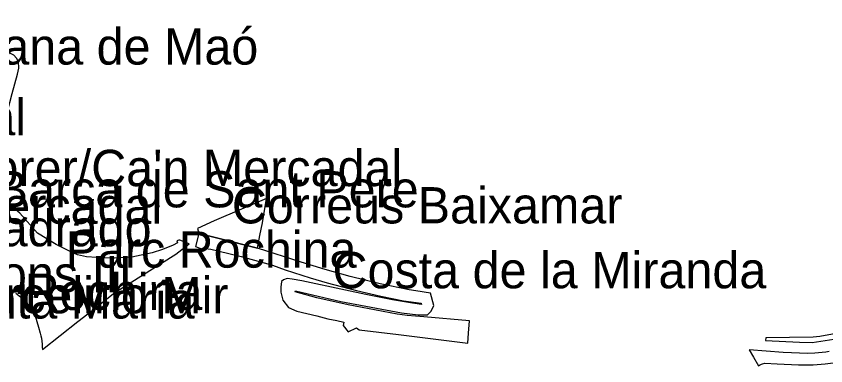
# Model space of a CAD drawing. Extents: x 599451 to 612034, y 4411179 to 4428219.
# Drawn here: x 608246.7 to 608514.7, y 4416232.3 to 4416348 of the extents above; entities that cross this region are included whole.
import ezdxf

# ---------------------------------------------------------------- set-up
doc = ezdxf.new("R2010")
doc.units = 0
doc.layers.add('Elements patrimoni', color=7, linetype='Continuous')
doc.layers.add('Elements patrimonials', color=7, linetype='Continuous')

msp = doc.modelspace()

# ---------------------------------------------------------------- linework, layer by layer
at = {"layer": 'Elements patrimonials'}
for points in [[(608243.71, 4416315.96), (608245.36, 4416322.37), (608247.07, 4416328.77), (608247.51, 4416330.82), (608247.4, 4416332.84), (608246.76, 4416334.12), (608245.84, 4416335.04), (608244.8, 4416335.6), (608243.01, 4416336.08), (608240.46, 4416336.82), (608209.6, 4416345.68), (608201, 4416347.97), (608195.6, 4416328.69), (608204.55, 4416326.24), (608207.12, 4416336.16), (608237.3, 4416327.77), (608234.77, 4416317.97)], [(608312.99, 4416274.62), (608326.57, 4416271.17), (608327.36, 4416275.41), (608328.22, 4416279.61), (608329.48, 4416287.61), (608312.18, 4416280.22), (608306.64, 4416277.75), (608307.12, 4416276.08)], [(608307.11, 4416276.08), (608306.03, 4416271.7), (608307.96, 4416270.93), (608309.27, 4416271.05), (608311.08, 4416270.88), (608313.43, 4416270.37), (608321.18, 4416268.48), (608328.8, 4416266.4), (608331.48, 4416265.62), (608335.73, 4416264.06), (608343.97, 4416261.43), (608349.66, 4416259.69), (608359.35, 4416257.21), (608367.36, 4416255.31), (608374.85, 4416253.75), (608379.09, 4416253.21), (608380.71, 4416253), (608380.8, 4416252.55), (608377.89, 4416253), (608371.25, 4416254.12), (608362.41, 4416255.85), (608355.72, 4416257.26), (608341.18, 4416260.36), (608338.03, 4416260.99), (608336.41, 4416261.19), (608335.18, 4416260.7), (608334.48, 4416260.16), (608334.27, 4416258.25), (608334.22, 4416256.6), (608334.89, 4416253.99), (608336.85, 4416251.53), (608339.62, 4416250.34), (608346.23, 4416248.76), (608349.83, 4416247.86), (608352.81, 4416247.26), (608355.13, 4416246.66), (608354.88, 4416245.59), (608356.59, 4416243.46), (608359.28, 4416244.85), (608360.18, 4416244.19), (608373.21, 4416242.59), (608396.23, 4416239.77), (608396.45, 4416243.06), (608396.76, 4416247.12), (608381.56, 4416248.44), (608376.1, 4416248.96), (608372.83, 4416249.35), (608356.58, 4416252.44), (608346.22, 4416254.8), (608339.02, 4416256.78), (608339.12, 4416257.07), (608354.11, 4416253.52), (608374.19, 4416249.84), (608379.71, 4416249.12), (608382.88, 4416249.17), (608384.02, 4416250.34), (608384.89, 4416252.27), (608383.8, 4416256.35), (608378.92, 4416257.09), (608376.76, 4416257.41), (608367.13, 4416259.38), (608357.2, 4416261.8), (608348.9, 4416264.1), (608341, 4416266.6), (608326.56, 4416271.17), (608313.81, 4416274.43)]]:
    msp.add_lwpolyline(points, close=True, dxfattribs=at)
for points in [[(608246.54, 4416256.27), (608248.19, 4416255.03), (608249.69, 4416253.55), (608250.68, 4416252.42), (608251.91, 4416250.71), (608252.9, 4416248.82), (608253.44, 4416246.94), (608254, 4416245.1), (608254.57, 4416243.08), (608254.8, 4416242.2), (608255, 4416241.4), (608255.25, 4416239.43), (608255.27, 4416238.47), (608255.32, 4416237.67), (608267.02, 4416246.88), (608271.84, 4416250.55), (608279.3, 4416256.51), (608288.81, 4416262.51), (608294.74, 4416266.22), (608299.48, 4416269.23), (608303.91, 4416272.63), (608300.84, 4416273.86), (608300.52, 4416273.9), (608299.81, 4416273.62), (608300.11, 4416272.97), (608298.65, 4416272.21), (608295.11, 4416270.78), (608291.67, 4416269.64), (608284.9, 4416268.25), (608279.22, 4416267.87), (608278.28, 4416267.9), (608273.32, 4416268.07), (608269.98, 4416268.35), (608266.99, 4416269.01), (608264.92, 4416269.89), (608259.94, 4416272.47), (608253.71, 4416276.17), (608247.83, 4416282.77), (608241.48, 4416288.05)], [(608520.54, 4416243.4), (608512.72, 4416242.02), (608510.48, 4416241.8), (608494.81, 4416241.48), (608494.78, 4416240.64), (608505.98, 4416240.1), (608510.14, 4416239.94), (608517.37, 4416241.1)], [(608515.84, 4416236.99), (608514.66, 4416236.83), (608512.29, 4416236.59), (608511.1, 4416236.5), (608508.71, 4416236.38), (608500.6, 4416236.63), (608489.32, 4416237.52), (608490.71, 4416235.12), (608492.37, 4416232.27), (608492.69, 4416232.49), (608493.38, 4416232.85), (608493.76, 4416232.97), (608494.53, 4416233.09), (608498.59, 4416232.97), (608505.7, 4416232.54), (608510.55, 4416232.58), (608514.44, 4416232.93), (608518.06, 4416233.39)]]:
    msp.add_lwpolyline(points, dxfattribs=at)

# ---------------------------------------------------------------- texts
at = {"layer": 'Elements patrimoni'}
msp.add_text('Monument Alfons III', height=12, dxfattribs=at).set_placement((608142.29, 4416256.62))
at = {"layer": 'Elements patrimonials'}
for s, p in [('Duana de Maó', (608221.55, 4416331.96)), ("Ca'n Mercadal", (608146.97, 4416308.59)), ("Casa Febrer/Ca'n Mercadal", (608177.85, 4416291.75)), ('Barca de Sant Pere', (608239.87, 4416284.71)), ("Ca'n Mercadal", (608192.06, 4416279.26)), ('Correus Baixamar', (608318.06, 4416279.39)), ('Casa Cuadrado', (608179.09, 4416271.82)), ('Parc Rochina', (608263, 4416264.75)), ('Costa de la Miranda', (608351.39, 4416257.93)), ('Parc Rochina', (608211.98, 4416250.76)), ('Esglesia de Santa María', (608130.88, 4416247.91)), ('Casa Marcelino Mir', (608178.74, 4416249.64))]:
    msp.add_text(s, height=12, dxfattribs=at).set_placement(p)

doc.saveas('drawing.dxf')
